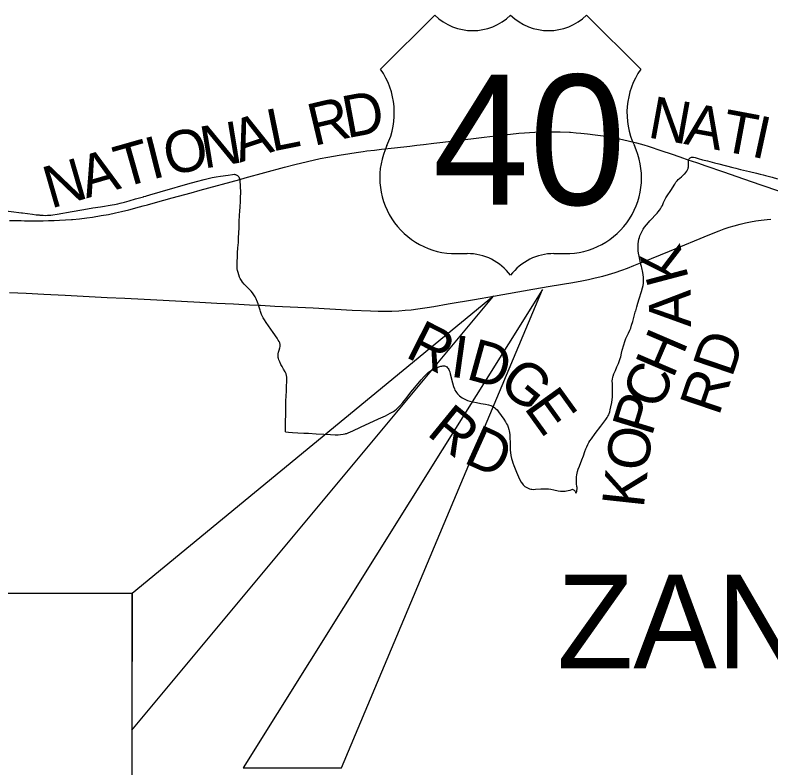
# Model space of a CAD drawing. Extents: x 1761803 to 2441803, y 509895 to 949895.
# Drawn here: x 2076440 to 2092620, y 793748 to 809863 of the extents above; entities that cross this region are included whole.
import ezdxf

# ---------------------------------------------------------------- set-up
doc = ezdxf.new("R2010")
doc.units = 0
for name, color, linetype in [('GM_X_County_Road', 7, 'Continuous'), ('GM_X_County_Road_Text', 7, 'Continuous'), ('GM_X_Minor_River', 7, 'Continuous'), ('GM_X_Minor_River_Text', 7, 'Continuous'), ('GM_X_State_Location', 7, 'Continuous')]:
    doc.layers.add(name, color=color, linetype=linetype)

msp = doc.modelspace()

# ---------------------------------------------------------------- linework, layer by layer
at = {"layer": 'GM_X_County_Road'}
for points in [[(2090850, 806595), (2090853, 806612), (2090854, 806628), (2090853, 806706), (2090854, 806722), (2090856, 806735), (2090862, 806761)], [(2090862, 806761), (2090871, 806784), (2090877, 806793), (2090882, 806799), (2090892, 806811), (2090905, 806818), (2090919, 806822), (2090935, 806823), (2090950, 806822), (2090966, 806820), (2090997, 806813), (2091060, 806794), (2091157, 806768), (2091265, 806740), (2091409, 806704), (2091504, 806680), (2091805, 806604), (2091868, 806587), (2091972, 806561), (2092159, 806515), (2092314, 806480), (2092392, 806461), (2092455, 806443)], [(2090669, 806373), (2090704, 806400), (2090728, 806421), (2090763, 806456), (2090775, 806468), (2090797, 806492), (2090817, 806519), (2090833, 806548), (2090840, 806563), (2090846, 806579), (2090850, 806595)], [(2079645, 806107), (2080137, 806248), (2080326, 806303), (2080484, 806346), (2080541, 806361), (2080601, 806375), (2080657, 806386), (2080743, 806400), (2080839, 806415), (2080999, 806439), (2081096, 806452), (2081128, 806455), (2081144, 806453), (2081159, 806450), (2081174, 806445), (2081187, 806437), (2081200, 806428), (2081218, 806412), (2081230, 806398), (2081239, 806377), (2081251, 806345)], [(2092455, 806443), (2092505, 806429), (2092646, 806392), (2092760, 806361)], [(2081267, 805972), (2081270, 806051), (2081270, 806100), (2081268, 806165), (2081264, 806231), (2081258, 806295), (2081255, 806320), (2081251, 806345)], [(2089725, 803530), (2089751, 803619), (2089774, 803697), (2089803, 803791), (2089851, 803947), (2089873, 804026), (2089883, 804074), (2089890, 804123), (2089894, 804172), (2089895, 804205), (2089891, 804255), (2089885, 804303), (2089876, 804352), (2089854, 804450), (2089848, 804479), (2089837, 804527), (2089830, 804559), (2089822, 804597), (2089800, 804703), (2089788, 804770), (2089780, 804817), (2089778, 804859), (2089776, 804912), (2089779, 804968), (2089785, 805017), (2089796, 805066), (2089807, 805105), (2089816, 805136), (2089827, 805166), (2089840, 805196), (2089863, 805239), (2089888, 805280), (2089916, 805320), (2089999, 805422), (2090030, 805460), (2090063, 805496), (2090152, 805590), (2090185, 805626), (2090207, 805650), (2090237, 805689), (2090256, 805716), (2090281, 805759), (2090296, 805788), (2090322, 805848), (2090349, 805907), (2090372, 805950), (2090397, 805991), (2090475, 806106), (2090563, 806247), (2090588, 806286), (2090612, 806317), (2090638, 806346), (2090669, 806373)], [(2079471, 806057), (2079617, 806099), (2079645, 806107)], [(2077660, 805659), (2077703, 805667), (2077993, 805716), (2078106, 805734), (2078268, 805760), (2078517, 805801), (2078568, 805810), (2078639, 805824), (2078690, 805835), (2078783, 805859), (2078879, 805886), (2079019, 805927), (2079128, 805959), (2079187, 805975)], [(2079187, 805975), (2079196, 805978), (2079239, 805990)], [(2079239, 805990), (2079255, 805994), (2079321, 806013)], [(2079321, 806013), (2079349, 806021), (2079471, 806057)], [(2081247, 805583), (2081252, 805667), (2081257, 805758), (2081264, 805873), (2081267, 805970), (2081267, 805972)], [(2074616, 805810), (2074620, 805813), (2074625, 805814), (2074629, 805814), (2074711, 805811), (2074924, 805804), (2075007, 805801), (2075067, 805799), (2075130, 805795), (2075189, 805791), (2075260, 805784), (2075293, 805780), (2075346, 805775), (2075428, 805765), (2075818, 805720), (2075997, 805700), (2076062, 805692), (2076175, 805677), (2076354, 805656), (2076575, 805630)], [(2076575, 805630), (2076598, 805628), (2076809, 805599), (2076892, 805590), (2076958, 805584)], [(2076958, 805584), (2076971, 805583), (2077038, 805578), (2077084, 805576), (2077132, 805577), (2077172, 805579), (2077203, 805582), (2077250, 805588), (2077340, 805603), (2077660, 805659)], [(2081225, 805124), (2081227, 805175), (2081233, 805338), (2081236, 805420), (2081240, 805485), (2081243, 805533), (2081247, 805583)], [(2081198, 804680), (2081200, 804714), (2081202, 804776), (2081210, 804883), (2081219, 804995), (2081222, 805044), (2081224, 805093), (2081225, 805124)], [(2081565, 803856), (2081552, 803877), (2081524, 803917), (2081494, 803955), (2081460, 803990), (2081377, 804069), (2081343, 804105), (2081311, 804143), (2081283, 804184), (2081259, 804227), (2081244, 804256), (2081226, 804302), (2081212, 804350), (2081201, 804397), (2081195, 804428), (2081192, 804461), (2081191, 804493), (2081191, 804524), (2081193, 804589), (2081198, 804680)], [(2081815, 803280), (2081813, 803282), (2081777, 803337), (2081751, 803379), (2081729, 803423), (2081715, 803453), (2081699, 803496), (2081691, 803520), (2081684, 803543), (2081677, 803566), (2081657, 803632), (2081651, 803653), (2081643, 803681), (2081631, 803718), (2081618, 803750), (2081611, 803768), (2081601, 803792), (2081578, 803835), (2081566, 803854), (2081565, 803856)], [(2088468, 799769), (2088466, 799781), (2088461, 799822), (2088458, 799861), (2088458, 799929), (2088461, 799979), (2088465, 800018), (2088470, 800054), (2088479, 800091), (2088494, 800140), (2088519, 800206), (2088575, 800343), (2088606, 800427), (2088639, 800519), (2088660, 800577), (2088678, 800624), (2088698, 800672), (2088719, 800712), (2088744, 800751), (2088777, 800795), (2088860, 800905), (2088976, 801064), (2089086, 801206), (2089115, 801246), (2089132, 801274), (2089147, 801304), (2089159, 801335), (2089169, 801367), (2089180, 801415), (2089194, 801478), (2089212, 801573), (2089222, 801637), (2089228, 801686), (2089232, 801735), (2089232, 801783), (2089229, 801865), (2089226, 801977), (2089225, 802025), (2089228, 802074), (2089233, 802105), (2089236, 802121), (2089241, 802136), (2089259, 802181), (2089292, 802256), (2089325, 802331), (2089356, 802407), (2089380, 802468), (2089395, 802515), (2089404, 802547), (2089422, 802627), (2089437, 802690), (2089468, 802801), (2089493, 802878), (2089516, 802939), (2089536, 802984), (2089572, 803057), (2089599, 803117), (2089618, 803163), (2089639, 803225), (2089662, 803304), (2089700, 803446), (2089716, 803501), (2089723, 803525), (2089725, 803530)], [(2082225, 800942), (2082225, 800954), (2082226, 800992), (2082229, 801142), (2082233, 801337), (2082234, 801402), (2082235, 801468), (2082237, 801533), (2082239, 801583), (2082245, 801729), (2082248, 801795), (2082253, 801909), (2082257, 802024), (2082258, 802073), (2082258, 802101), (2082256, 802121), (2082253, 802137), (2082250, 802153), (2082246, 802168), (2082240, 802184), (2082234, 802198), (2082219, 802227), (2082186, 802282), (2082154, 802338), (2082131, 802381), (2082104, 802439), (2082087, 802484), (2082078, 802515), (2082075, 802531), (2082073, 802547), (2082071, 802563), (2082072, 802580), (2082073, 802596), (2082075, 802613), (2082081, 802645), (2082095, 802693), (2082107, 802740), (2082112, 802772), (2082113, 802788), (2082113, 802804), (2082112, 802820), (2082109, 802835), (2082104, 802850), (2082098, 802865), (2082091, 802878), (2082075, 802906), (2082048, 802947), (2081965, 803068), (2081815, 803280)], [(2083519, 800903), (2083539, 800909), (2083572, 800922), (2083668, 800963), (2083832, 801039), (2084219, 801219), (2084367, 801288), (2084470, 801339), (2084513, 801363), (2084541, 801380), (2084568, 801398), (2084606, 801428), (2084641, 801462), (2084675, 801498), (2084739, 801572), (2084832, 801686), (2084914, 801788), (2084998, 801890), (2085135, 802053), (2085199, 802128), (2085233, 802164), (2085262, 802192), (2085292, 802218), (2085330, 802245), (2085367, 802267), (2085416, 802293), (2085465, 802315), (2085509, 802334), (2085533, 802342), (2085555, 802348), (2085573, 802351), (2085596, 802355), (2085619, 802355), (2085634, 802352), (2085651, 802346), (2085665, 802341), (2085683, 802330), (2085697, 802315), (2085711, 802296), (2085725, 802274), (2085735, 802254), (2085744, 802228), (2085757, 802182), (2085805, 801991), (2085828, 801912), (2085844, 801866), (2085857, 801837), (2085873, 801808), (2085890, 801781), (2085910, 801756), (2085933, 801732), (2085957, 801710), (2085982, 801690), (2086009, 801672), (2086051, 801648), (2086081, 801634), (2086126, 801616), (2086172, 801601), (2086236, 801586), (2086316, 801569), (2086412, 801551), (2086509, 801532), (2086573, 801518), (2086621, 801503), (2086652, 801491), (2086681, 801476), (2086708, 801457), (2086734, 801435), (2086757, 801412), (2086788, 801373), (2086845, 801293), (2086902, 801212), (2086938, 801158), (2086963, 801115), (2086978, 801085), (2086997, 801040), (2087012, 800992), (2087019, 800960), (2087025, 800928), (2087031, 800878), (2087034, 800813), (2087035, 800714), (2087036, 800616), (2087039, 800551), (2087044, 800502), (2087054, 800437), (2087068, 800373), (2087079, 800326), (2087094, 800279), (2087117, 800218), (2087174, 800082), (2087220, 799977), (2087246, 799916), (2087274, 799867), (2087299, 799830), (2087317, 799806), (2087340, 799785), (2087352, 799774), (2087365, 799765), (2087393, 799748), (2087422, 799734), (2087452, 799722), (2087483, 799714), (2087499, 799711), (2087531, 799709), (2087580, 799711), (2087694, 799719), (2087760, 799723), (2087809, 799723), (2087858, 799720), (2087908, 799714), (2087972, 799703), (2088069, 799682), (2088117, 799675), (2088149, 799672), (2088182, 799672), (2088214, 799673), (2088246, 799677), (2088279, 799683), (2088326, 799695), (2088357, 799705), (2088372, 799711)], [(2082225, 800942), (2082294, 800936), (2082376, 800930), (2082490, 800924), (2082621, 800916), (2082719, 800910), (2082882, 800902), (2083046, 800894), (2083194, 800886), (2083292, 800881), (2083357, 800880), (2083406, 800882), (2083463, 800890), (2083506, 800899), (2083519, 800903)], [(2088446, 799628), (2088452, 799638), (2088459, 799652), (2088464, 799671), (2088467, 799688), (2088472, 799720), (2088472, 799733), (2088471, 799748), (2088468, 799769)], [(2088446, 799628), (2088445, 799638), (2088442, 799651), (2088439, 799659), (2088430, 799671), (2088425, 799678), (2088415, 799685), (2088404, 799692), (2088389, 799699), (2088372, 799711)]]:
    msp.add_lwpolyline(points, dxfattribs=at)
at = {"layer": 'GM_X_County_Road_Text'}
for p, q in [((2085424, 809863), (2084264, 808703)), ((2089833, 808703), (2088673, 809863)), ((2085888, 804758), (2086120, 804758)), ((2087976, 804758), (2088209, 804758))]:
    msp.add_line(p, q, dxfattribs=at)
for centre, radius, start, end in [((2086236, 810692), 1160, 225.573, 314.427), ((2087860, 810692), 1160, 225.573, 314.427), ((2082934, 807771), 1624, 334.5471, 35.0009), ((2091163, 807771), 1624, 144.9991, 205.4529), ((2085870, 806382), 1624, 154.8319, 270.6383), ((2088227, 806382), 1624, 269.3617, 25.1681), ((2086120, 803598), 1160, 36.8699, 90), ((2087976, 803598), 1160, 90, 143.1301)]:
    msp.add_arc(centre, radius, start, end, dxfattribs=at)
at = {"layer": 'GM_X_Minor_River'}
msp.add_lwpolyline([(2076317, 803927), (2076678, 803909), (2077054, 803889), (2077513, 803866), (2078414, 803820), (2078791, 803801), (2079200, 803780), (2079610, 803758), (2080396, 803717), (2080756, 803699), (2081116, 803681), (2081460, 803663), (2081651, 803653), (2081690, 803651), (2082001, 803635), (2082820, 803593), (2083655, 803549), (2084049, 803531), (2084213, 803526), (2084360, 803525), (2084508, 803527), (2084656, 803533), (2084787, 803543), (2084917, 803555), (2085064, 803573), (2085259, 803601), (2085405, 803625), (2085712, 803679), (2086277, 803777), (2086681, 803848), (2087521, 803993), (2087893, 804058), (2088378, 804141), (2088571, 804176), (2088716, 804205), (2088860, 804237), (2089019, 804278), (2089146, 804313), (2089287, 804356), (2089428, 804402), (2089551, 804447), (2089689, 804500), (2089830, 804559), (2089871, 804576), (2090447, 804813), (2091311, 805168), (2091509, 805247), (2091617, 805287), (2091726, 805322), (2091836, 805355), (2091962, 805389), (2092074, 805416), (2092186, 805439), (2092299, 805458), (2092413, 805474), (2092543, 805488), (2092620, 805495)], dxfattribs=at)
at = {"layer": 'GM_X_Minor_River_Text'}
msp.add_lwpolyline([(2076318, 805469), (2076570, 805463), (2076644, 805461), (2076767, 805460), (2077040, 805461), (2077158, 805464), (2077278, 805466), (2077393, 805472), (2077516, 805478), (2077645, 805487), (2077672, 805490), (2077816, 805503), (2077972, 805521), (2078099, 805538), (2078283, 805570), (2078441, 805597), (2078588, 805628), (2078714, 805657), (2078875, 805697), (2079103, 805758), (2079180, 805779), (2079276, 805805), (2079444, 805851), (2079801, 805948), (2080212, 806061), (2080402, 806114), (2081251, 806345), (2081368, 806377), (2082207, 806607), (2082429, 806665), (2082700, 806732), (2082973, 806793), (2083134, 806825), (2083376, 806867), (2083606, 806904), (2083739, 806924), (2083891, 806944), (2083970, 806955), (2084131, 806974), (2084285, 806991), (2084561, 807022), (2084889, 807061), (2085039, 807078), (2085180, 807095), (2085401, 807121), (2085847, 807174), (2086479, 807247), (2086844, 807291), (2087048, 807314), (2087227, 807333), (2087345, 807343), (2087452, 807351), (2087564, 807357), (2087653, 807361), (2087783, 807364), (2087977, 807364), (2088100, 807365), (2088109, 807365), (2088306, 807357), (2088330, 807356), (2088449, 807346), (2088551, 807337), (2088697, 807322), (2088860, 807301), (2089031, 807277), (2089164, 807255), (2089376, 807213), (2089565, 807171), (2089742, 807127), (2089900, 807083), (2089989, 807056), (2090284, 806958), (2090486, 806893), (2090670, 806826), (2090862, 806761), (2090915, 806744), (2091046, 806698), (2091227, 806635), (2091603, 806505), (2092033, 806359), (2092405, 806231), (2092515, 806193), (2092902, 806060)], dxfattribs=at)
at = {"layer": 'GM_X_State_Location'}
for points in [[(2087728, 803990), (2081320, 793748), (2083428, 793748)], [(2086681, 803848), (2078945, 797481), (2078942, 794555)], [(2049569, 782647), (2078945, 782647), (2078945, 797481), (2049569, 797481)]]:
    msp.add_lwpolyline(points, close=True, dxfattribs=at)

# ---------------------------------------------------------------- texts
at = {"layer": 'GM_X_County_Road'}
for s, height, rotation, p in [('D', 900, 10.5284, (2083540, 807226)), ('R', 900, 13.3357, (2082832, 807057)), ('N', 900, 349.6984, (2089960, 807249)), ('L', 900, 11.4442, (2081937, 806939)), ('A', 900, 349.6949, (2090739, 807108)), ('A', 900, 18.3092, (2081252, 806702)), ('T', 900, 349.3981, (2091517, 806966)), ('I', 900, 347.7511, (2092172, 806844)), ('N', 900, 9.3192, (2080481, 806576)), ('O', 900, 10.977, (2079710, 806426)), ('T', 900, 15.8347, (2078723, 806156)), ('I', 900, 14.1877, (2079365, 806338)), ('A', 900, 16.1315, (2077964, 805937)), ('N', 900, 16.135, (2077203, 805717)), ('K', 900, 104.8321, (2090870, 804220)), ('A', 900, 90.6763, (2090912, 803188)), ('R', 900, 333.1417, (2084767, 802557)), ('I', 900, 352.0312, (2085734, 802127)), ('H', 900, 66.8969, (2090523, 802062)), ('RD', 900, 71.2474, (2091503, 801260)), ('D', 900, 344.5545, (2086070, 802082)), ('G', 900, 320.6063, (2086746, 801916)), ('C', 900, 67.1048, (2090236, 801382)), ('E', 900, 305.7813, (2087316, 801459)), ('P', 900, 73.0004, (2090067, 800824)), ('R', 900, 320.7711, (2085227, 800892)), ('D', 900, 335.7843, (2086014, 800292)), ('O', 900, 83.1754, (2089981, 800079)), ('K', 900, 83.7978, (2089896, 799295)), ('ZANESVILLE', 2000, 0, (2088042, 795881))]:
    msp.add_text(s, height=height, rotation=rotation, dxfattribs=at).set_placement(p)
at = {"layer": 'GM_X_County_Road_Text'}
msp.add_text('40', height=2784.4, dxfattribs=at).set_placement((2085376, 805802))

doc.saveas('drawing.dxf')
